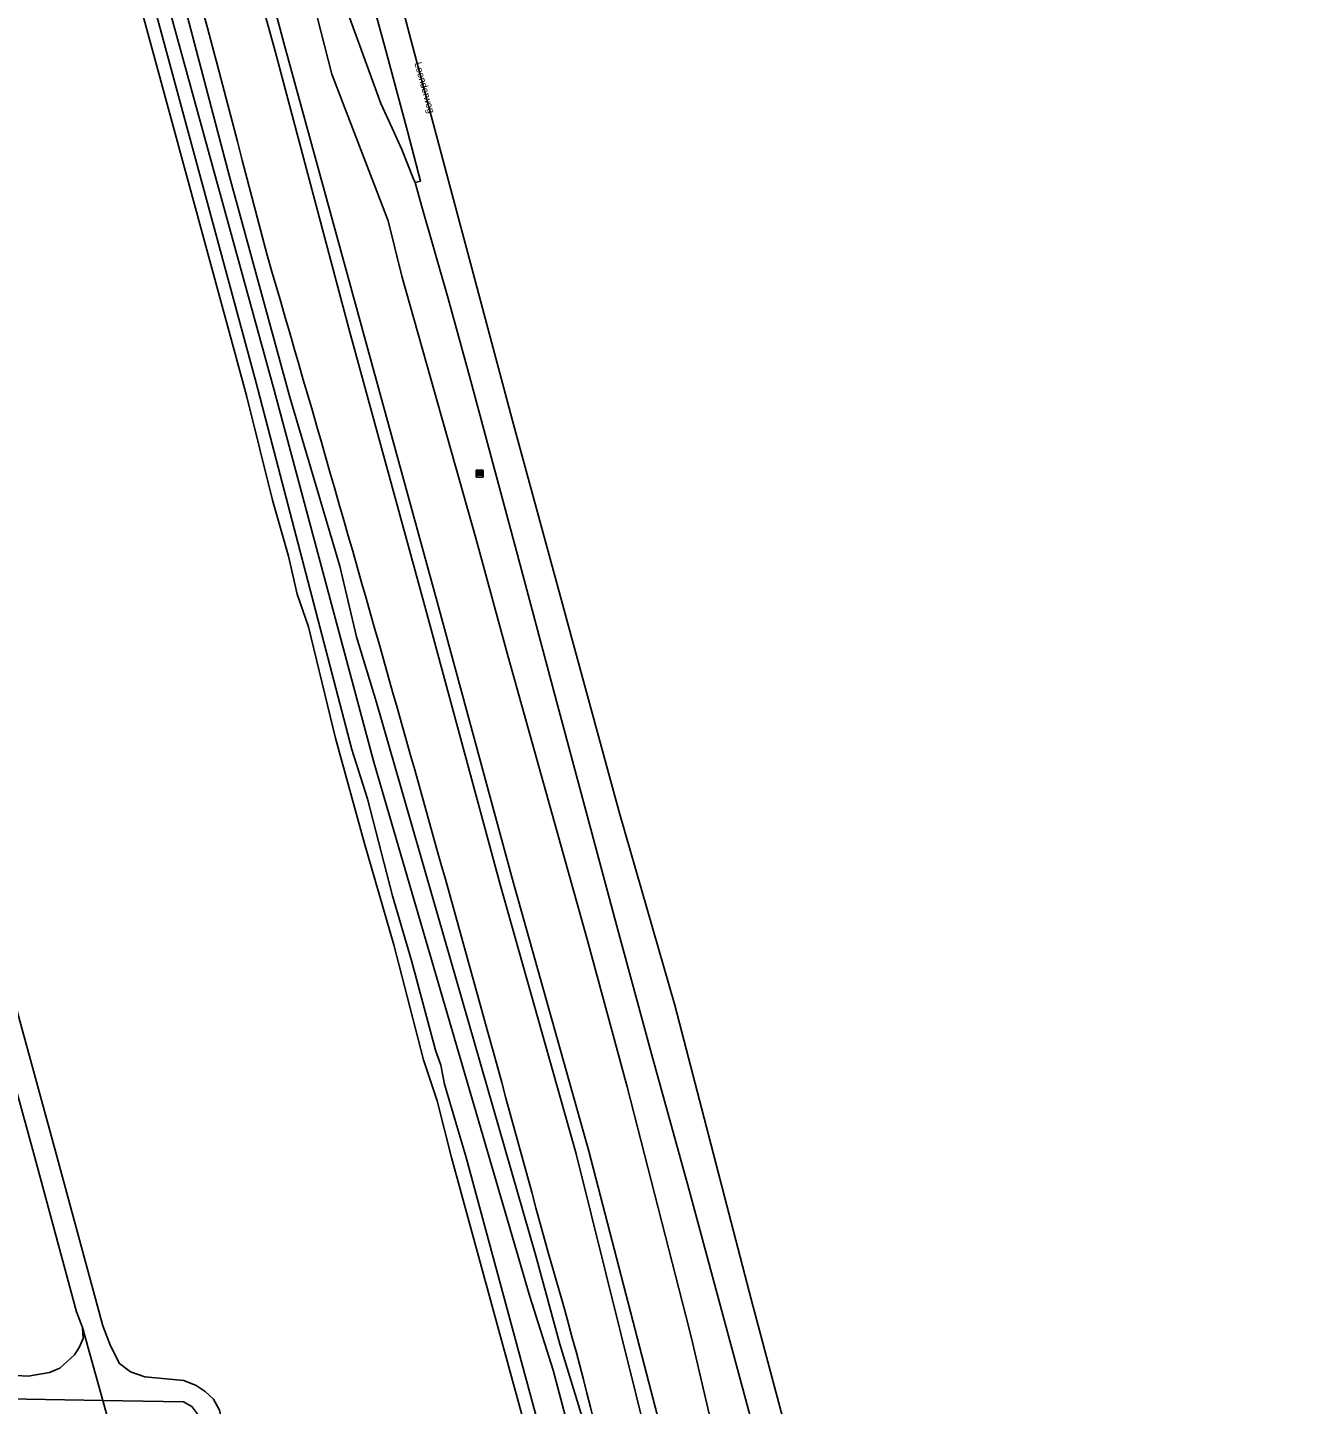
# Model space of a CAD drawing. Extents: x 162157 to 163165, y 378998 to 380775.
# Drawn here: x 162802.1 to 162981.8, y 379965.5 to 380157.8 of the extents above; entities that cross this region are included whole.
import ezdxf

# ---------------------------------------------------------------- set-up
doc = ezdxf.new("R2010")
doc.units = 0
for name, color, linetype in [('IMGEO_Berm_groen', 7, 'Continuous'), ('IMGEO_Gemengd_bos', 7, 'Continuous'), ('IMGEO_Groenvoorziening', 7, 'Continuous'), ('IMGEO_Openbare_ruimte_label', 7, 'Continuous'), ('IMGEO_Rijbaan_lokaal_gesloten', 7, 'Continuous'), ('IMGEO_Rijbaan_lokaal_onverhard', 7, 'Continuous'), ('IMGEO_Rijbaan_regionaal_gesloten', 7, 'Continuous'), ('IMGEO_Voetpad_onverhard', 7, 'Continuous'), ('IMGEO_Wegwijzer', 7, 'Continuous')]:
    doc.layers.add(name, color=color, linetype=linetype)

msp = doc.modelspace()

# ---------------------------------------------------------------- linework, layer by layer
at = {"layer": 'IMGEO_Berm_groen'}
msp.add_lwpolyline([(162827.76, 380214.25), (162828.22, 380211.65), (162831.86, 380198.18), (162836.23, 380181.26), (162840.44, 380167.5), (162844.58, 380151.28), (162852.47, 380130.79), (162854.37, 380123.05), (162864.7, 380086.48), (162869.2, 380069.9), (162880.27, 380030.3), (162885.8, 380009.88), (162894.02, 379977.91), (162894.82, 379974.81), (162899.22, 379955.87), (162902.22, 379931.42), (162904.56, 379914.07), (162906.14, 379899.21), (162909.01, 379881.44), (162910.96, 379872.62), (162920.05, 379843.16), (162923.52, 379831.46), (162929.16, 379811.21), (162935.38, 379790.5)], dxfattribs=at)
at = {"layer": 'IMGEO_Gemengd_bos'}
msp.add_lwpolyline([(162813.21, 379963.91), (162812.61, 379966.09)], dxfattribs=at)
at = {"layer": 'IMGEO_Groenvoorziening'}
for points in [[(162827.41, 380194.68), (162838.08, 380154.93), (162859.43, 380077.09), (162869.82, 380038.83), (162880.45, 380000.89), (162886.92, 379975.97), (162893.55, 379950.48)], [(162891.3, 379949.82), (162884.94, 379975.44), (162878.71, 380000.53), (162868.08, 380038.13), (162857.7, 380076.5), (162846.96, 380115.76), (162836.68, 380154.47), (162825.7, 380194.15)]]:
    msp.add_lwpolyline(points, dxfattribs=at)
for centre, radius, start, end in [((156261.77, 378414.57), 6792.91, 14.592707, 15.330545), ((155605.64, 378014.13), 7532.04, 15.180091, 16.283276), ((162391.87, 379842.83), 503.9, 9.2605, 16.5574)]:
    msp.add_arc(centre, radius, start, end, dxfattribs=at)
at = {"layer": 'IMGEO_Rijbaan_lokaal_gesloten'}
for points in [[(162856.21, 380136.12), (162855.96, 380136.76), (162854.37, 380140.73), (162852.99, 380143.75), (162851.45, 380147.17), (162847.93, 380156.76), (162846.88, 380159.68), (162845.69, 380164.1), (162842.43, 380176.6), (162835.45, 380202.41), (162832.56, 380215.85), (162832.33, 380216.92), (162831.77, 380220.44), (162830.51, 380228.44), (162829.43, 380235.22)], [(162805.6, 380206.95), (162811.23, 380185.22), (162832.66, 380106.4), (162836.29, 380091.77), (162838.54, 380083.95), (162839.74, 380078.68), (162841.31, 380074.11), (162845.11, 380058.55), (162849.13, 380043.85), (162853.26, 380029.71), (162857.39, 380013.63), (162859.31, 380007.93), (162861.32, 380000), (162874.8, 379950.69)], [(162875.93, 379953.56), (162863.33, 380000), (162860.3, 380010.25), (162859.82, 380012.91), (162859.06, 380014.99), (162855.7, 380027.53), (162853.05, 380036.53), (162849.58, 380050.07), (162847.39, 380056.99), (162834.02, 380108.17), (162807.15, 380207.37)]]:
    msp.add_lwpolyline(points, dxfattribs=at)
at = {"layer": 'IMGEO_Rijbaan_lokaal_onverhard'}
for points in [[(162852.22, 379836.57), (162855.95, 379839.98), (162859.94, 379851), (162864.32, 379866.72), (162869.74, 379887.62), (162878.52, 379925.93), (162880.46, 379936.12), (162880.89, 379940.36), (162878.53, 379959.46), (162877.4, 379963.09), (162875.48, 379970.32), (162872.22, 379980.62), (162850.44, 380055.19), (162836.52, 380107.17), (162815.65, 380183.14)], [(162820.47, 380174.33), (162830.29, 380136.99), (162838.72, 380106.17), (162845.72, 380082.59), (162848.03, 380072.7), (162850.82, 380063.54), (162873.07, 379986.28), (162876.41, 379973.93), (162879.54, 379963.77), (162885.3, 379937.58), (162887.73, 379923.86), (162896.6, 379888.82), (162898.62, 379878.42), (162900.23, 379871.56), (162900.24, 379870.17), (162899.79, 379854.89), (162898.6, 379840.15)]]:
    msp.add_lwpolyline(points, dxfattribs=at)
at = {"layer": 'IMGEO_Rijbaan_regionaal_gesloten'}
for points in [[(162829.43, 380235.22), (162830.27, 380235.45), (162831.11, 380232.32), (162835.6, 380215.62), (162840.57, 380197.09), (162844.9, 380181.12), (162849.56, 380163.99), (162852.13, 380154.55), (162855.2, 380143.13), (162856.98, 380136.34), (162856.21, 380136.12)], [(162848.55, 380183.16), (162855.41, 380156.79), (162869.91, 380102.56), (162884.75, 380048.07), (162892.49, 380021.3), (162903.17, 379980.05), (162910.18, 379953.87), (162918.89, 379921.63), (162929.09, 379883.04), (162931.71, 379874.1), (162935.5, 379862.01), (162944.02, 379831), (162951.41, 379807.03), (162963.67, 379771.28), (162968.32, 379757.69), (162974.41, 379738.54), (162978.16, 379724.08), (162980.3, 379709.84), (162981.67, 379700.01), (162981.78, 379690.92), (162980.19, 379681.4), (162978.93, 379672.84), (162974.17, 379658.36), (162969.49, 379647.09)], [(162917.61, 379909.32), (162910.58, 379935.34), (162903.48, 379962.19), (162894.41, 379995.63), (162889.22, 380014.47), (162884.39, 380032.32), (162875.97, 380063.72), (162870.69, 380083.46), (162863.82, 380109.08), (162860.82, 380119.94), (162857.11, 380132.94), (162856.21, 380136.12)]]:
    msp.add_lwpolyline(points, dxfattribs=at)
at = {"layer": 'IMGEO_Voetpad_onverhard'}
for points in [[(162809.65, 379831.46), (162812.11, 379849.65), (162817.16, 379880.4), (162821.28, 379907.95), (162822.46, 379914.4), (162823.42, 379923.1), (162829.43, 379962.3), (162828.91, 379964.74), (162828.06, 379966.29), (162826.92, 379967.34), (162825.63, 379968.18), (162823.91, 379968.88), (162818.47, 379969.39), (162816.5, 379970.11), (162814.96, 379971.24), (162813.68, 379973.73), (162812.62, 379976.53), (162806.22, 380000), (162780.64, 380093.58), (162779.59, 380093.44)], [(162798.61, 380016.47), (162803.12, 380000), (162808.95, 379978.48), (162809.8, 379976.29)], [(162625.24, 379992.17), (162628.6, 379991.7), (162640.82, 379988.2), (162689.7, 379971.26), (162695.35, 379969.75), (162709.79, 379967.11), (162715.75, 379966.57), (162791.24, 379966.44), (162812.61, 379966.09)], [(162809.8, 379976.29), (162809.85, 379974.74), (162809.31, 379973.5), (162808.67, 379972.47), (162806.6, 379970.6), (162805.17, 379970), (162802.2, 379969.5), (162797.91, 379969.73), (162745.2, 379969.48), (162719.12, 379969.65)], [(162812.61, 379966.09), (162809.8, 379976.29)], [(162812.61, 379966.09), (162823.89, 379965.91), (162825.03, 379965.27), (162826.29, 379963.58), (162826.65, 379960.66), (162826.35, 379957.52), (162824.19, 379942.24), (162809.47, 379844.94), (162807.85, 379830.5), (162807.66, 379826.59)]]:
    msp.add_lwpolyline(points, dxfattribs=at)
at = {"layer": 'IMGEO_Wegwijzer'}
for p, q in [((162864.72, 380095.09), (162864.72, 380095.89)), ((162864.72, 380095.89), (162864.72, 380095.09)), ((162864.82, 380095.99), (162865.61, 380095.99)), ((162865.61, 380095.99), (162864.82, 380095.99)), ((162865.61, 380094.99), (162864.82, 380094.99)), ((162864.82, 380094.99), (162865.61, 380094.99)), ((162865.71, 380095.89), (162865.71, 380095.09)), ((162865.71, 380095.09), (162865.71, 380095.89))]:
    msp.add_line(p, q, dxfattribs=at)
for points in [[(162864.82, 380095.73), (162865.61, 380095.73), (162865.61, 380095.26), (162864.82, 380095.26), (162864.82, 380095.73)], [(162864.89, 380095.58), (162864.89, 380095.49), (162864.89, 380095.41), (162865.3, 380095.41), (162865.3, 380095.33), (162865.54, 380095.49), (162865.3, 380095.66), (162865.3, 380095.58), (162864.89, 380095.58)]]:
    msp.add_lwpolyline(points, dxfattribs=at)
for centre, start, end in [((162864.82, 380095.89), 90, 180), ((162864.82, 380095.89), 90, 180), ((162864.82, 380095.09), 180, 270), ((162864.82, 380095.09), 180, 270), ((162865.61, 380095.89), 0, 90), ((162865.61, 380095.89), 360, 90), ((162865.61, 380095.09), 270, 0), ((162865.61, 380095.09), 270, 0)]:
    msp.add_arc(centre, 0.1, start, end, dxfattribs=at)

# ---------------------------------------------------------------- texts
at = {"layer": 'IMGEO_Openbare_ruimte_label'}
msp.add_text('Leenderweg', height=1, rotation=285.1345, dxfattribs=at).set_placement((162856.12, 380152.81))

doc.saveas('drawing.dxf')
